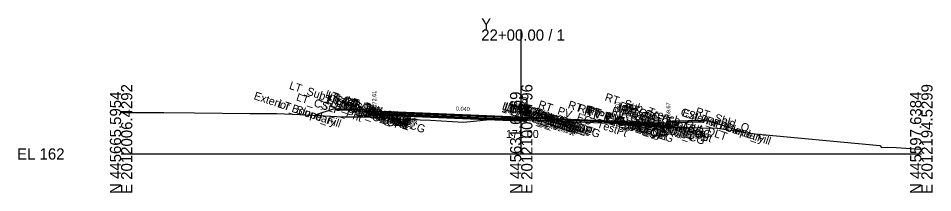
# Model space of a CAD drawing. Extents: x -26 to 3203, y -10 to 9532.
# Drawn here: x 974.3 to 1202.8, y 5990.3 to 6034 of the extents above; entities that cross this region are included whole.
import ezdxf

# ---------------------------------------------------------------- set-up
doc = ezdxf.new("R2010")
doc.units = 0
for name, color, linetype in [('Default', 7, 'Continuous'), ('Exist Cross Section Cell', 7, 'Continuous'), ('Exist XS Center Line Elevation Label', 7, 'Continuous'), ('Exist XS Ground Line', 7, 'Continuous'), ('Prop CMT Conc Surface', 7, 'Continuous'), ('Prop CMT Concrete Structures', 7, 'Continuous'), ('Prop CMT Pvmt Course 1', 7, 'Continuous'), ('Prop CMT Pvmt Course 1 CG', 7, 'Continuous'), ('Prop CMT Pvmt Course 1 Wedge', 7, 'Continuous'), ('Prop CMT Pvmt Course 2', 7, 'Continuous'), ('Prop CMT Pvmt Course 2 Wedge', 7, 'Continuous'), ('Prop CMT Pvmt Course 3', 7, 'Continuous'), ('Prop CMT Pvmt Surface', 7, 'Continuous'), ('Prop CMT Pvmt Wedge Surface 1', 7, 'Continuous'), ('Prop CMT Pvmt Wedge Surface 2', 7, 'Continuous'), ('Prop CMT Pvmt Wedge Surface 3', 7, 'Continuous'), ('Prop CMT Slope Grass', 7, 'Continuous'), ('Prop CMT Subgrade Earthwork', 7, 'Continuous'), ('Prop XS Hydro Elevations', 7, 'Continuous'), ('Prop XS Label Text', 7, 'Continuous'), ('Prop XS SE Text', 7, 'Continuous'), ('Prop XS Side Slope Text', 7, 'Continuous'), ('Scratch_Level_0', 7, 'Continuous')]:
    doc.layers.add(name, color=color, linetype=linetype)

msp = doc.modelspace()

# ---------------------------------------------------------------- linework, layer by layer
at = {"layer": 'Exist Cross Section Cell'}
for p, q in [((1100, 6000), (1100, 6031.15)), ((1000, 6000), (1100, 6000)), ((1100, 6000), (1200, 6000))]:
    msp.add_line(p, q, dxfattribs=at)
at = {"layer": 'Exist XS Ground Line'}
msp.add_lwpolyline([(1000, 6010.38), (1010.72, 6010.38), (1018.37, 6010.32), (1032.17, 6010.12), (1038.88, 6010.12), (1044.75, 6009.88), (1049.34, 6009.63), (1055.38, 6009.33), (1061.59, 6009.27), (1072.18, 6008.65), (1077.29, 6008.45), (1085.58, 6007.93), (1095.45, 6008.97), (1100.29, 6009), (1101.4, 6008.98), (1101.78, 6008.96), (1102.43, 6008.93), (1104.59, 6008.84), (1106.97, 6008.73), (1108.29, 6008.66), (1109.63, 6008.6), (1111.93, 6008.49), (1112.31, 6008.47), (1112.93, 6008.45), (1113.74, 6008.41), (1114.92, 6008.36), (1116.07, 6008.3), (1117.57, 6008.22), (1119.29, 6008.14), (1120.22, 6008.09), (1121.93, 6007.98), (1122.88, 6007.92), (1123.97, 6007.86), (1124.64, 6007.82), (1125.51, 6007.76), (1126.18, 6007.7), (1135.4, 6006.66), (1140.61, 6006.61), (1149.03, 6006.45), (1157.58, 6005.16), (1189.62, 6002.12), (1190.04, 6001.62), (1191.62, 6001.72), (1193.67, 6001.6), (1194.99, 6001.52), (1198.34, 6001.3), (1200, 6001.22)], dxfattribs=at)
at = {"layer": 'Prop CMT Conc Surface'}
for points in [[(1058.75, 6011.2), (1053.75, 6011.3)], [(1063.25, 6010.61), (1063.25, 6011.11), (1062.75, 6011.11)], [(1065.25, 6010.61), (1063.25, 6010.61)], [(1136.75, 6007.67), (1136.75, 6008.17), (1137.25, 6008.17)], [(1134.75, 6007.83), (1136.75, 6007.67)]]:
    msp.add_lwpolyline(points, dxfattribs=at)
at = {"layer": 'Prop CMT Concrete Structures'}
for points in [[(1053.75, 6010.97), (1053.75, 6011.3)], [(1053.75, 6011.3), (1058.75, 6011.2)], [(1058.75, 6010.87), (1053.75, 6010.97)], [(1058.75, 6011.2), (1058.75, 6010.87)], [(1065.25, 6010.61), (1063.25, 6010.61), (1063.25, 6011.11), (1062.75, 6011.11)], [(1062.75, 6011.11), (1062.75, 6010.13), (1065.25, 6010.03)], [(1065.25, 6010.03), (1065.25, 6010.61)], [(1108.5, 6008.88), (1108.49, 6009.05), (1107.74, 6009.3), (1107, 6009.43), (1106.26, 6009.42), (1105.51, 6009.17), (1105.5, 6009)], [(1105.5, 6009), (1108.5, 6008.88)], [(1134.75, 6007.83), (1136.75, 6007.67), (1136.75, 6008.17), (1137.25, 6008.17)], [(1137.25, 6008.17), (1137.25, 6007.15), (1134.75, 6007.25)], [(1145.75, 6008.35), (1137.75, 6008.19)], [(1137.75, 6008.19), (1137.75, 6007.86)], [(1145.75, 6008.02), (1145.75, 6008.35)], [(1134.75, 6007.25), (1134.75, 6007.83)], [(1137.75, 6007.86), (1145.75, 6008.02)]]:
    msp.add_lwpolyline(points, dxfattribs=at)
at = {"layer": 'Prop CMT Pvmt Course 1'}
for points in [[(1105.5, 6009), (1065.25, 6010.61)], [(1065.25, 6010.61), (1065.25, 6010.36)], [(1065.25, 6010.36), (1101.4, 6008.92)], [(1101.4, 6008.92), (1101.4, 6009.17)], [(1101.4, 6008.92), (1101.4, 6009.17)], [(1105.5, 6009), (1108.5, 6008.88)], [(1105.5, 6008.75), (1105.5, 6009)], [(1105.5, 6008.75), (1105.5, 6009)], [(1108.5, 6008.88), (1134.75, 6007.83)], [(1124.64, 6008.11), (1108.5, 6008.76)], [(1124.64, 6007.99), (1124.64, 6008.11)], [(1134.75, 6007.58), (1124.64, 6007.99)], [(1134.75, 6007.83), (1134.75, 6007.58)]]:
    msp.add_lwpolyline(points, dxfattribs=at)
for points in [[(1101.4, 6008.92), (1101.4, 6009.04), (1101.4, 6009.04), (1101.4, 6008.92)], [(1105.5, 6008.75), (1105.5, 6008.88), (1105.5, 6008.88), (1105.5, 6008.75)]]:
    msp.add_lwpolyline(points, close=True, dxfattribs=at)
at = {"layer": 'Prop CMT Pvmt Course 1 CG'}
for points in [[(1065.25, 6010.03), (1062.25, 6010.15), (1061.93, 6009.83)], [(1061.93, 6009.83), (1065.25, 6009.69)], [(1065.25, 6009.69), (1065.25, 6010.03)], [(1134.75, 6007.25), (1137.75, 6007.13), (1138.1, 6006.78)], [(1134.75, 6006.91), (1134.75, 6007.25)], [(1138.1, 6006.78), (1134.75, 6006.91)]]:
    msp.add_lwpolyline(points, dxfattribs=at)
at = {"layer": 'Prop CMT Pvmt Course 1 Wedge'}
for points in [[(1101.4, 6009.04), (1109.63, 6008.71), (1111.93, 6008.62), (1112.31, 6008.6), (1112.93, 6008.58), (1113.74, 6008.55), (1114.92, 6008.5), (1116.07, 6008.45), (1117.57, 6008.39), (1119.29, 6008.32), (1119.97, 6008.3), (1120.22, 6008.29), (1121.93, 6008.22), (1122.88, 6008.18), (1123.97, 6008.14), (1124.64, 6008.11)], [(1124.64, 6007.99), (1123.97, 6008.01), (1122.88, 6008.06), (1121.93, 6008.09), (1120.22, 6008.16), (1119.97, 6008.17), (1119.29, 6008.2), (1117.57, 6008.27), (1116.07, 6008.33), (1114.92, 6008.37), (1113.74, 6008.42), (1112.93, 6008.45), (1112.31, 6008.48), (1111.93, 6008.49), (1111.03, 6008.53), (1109.63, 6008.6), (1108.5, 6008.65)], [(1124.64, 6008.11), (1124.64, 6007.99), (1124.64, 6007.99)]]:
    msp.add_lwpolyline(points, dxfattribs=at)
at = {"layer": 'Prop CMT Pvmt Course 2'}
for points in [[(1101.4, 6008.92), (1065.25, 6010.36)], [(1065.25, 6010.36), (1065.25, 6010.03)], [(1065.25, 6010.03), (1101.4, 6008.58)], [(1101.4, 6008.58), (1101.4, 6008.92)], [(1101.4, 6008.58), (1101.4, 6008.92)], [(1124.64, 6007.65), (1124.64, 6007.99)], [(1124.64, 6007.99), (1134.75, 6007.58)], [(1134.75, 6007.25), (1124.64, 6007.65)], [(1134.75, 6007.58), (1134.75, 6007.25)]]:
    msp.add_lwpolyline(points, dxfattribs=at)
at = {"layer": 'Prop CMT Pvmt Course 2 Wedge'}
for points in [[(1126.18, 6007.7), (1126.09, 6007.71), (1125.51, 6007.76), (1125.39, 6007.77), (1125.29, 6007.78), (1124.64, 6007.82), (1123.97, 6007.86), (1122.88, 6007.92), (1121.93, 6007.98), (1120.22, 6008.09), (1119.97, 6008.1), (1119.29, 6008.14), (1117.57, 6008.22), (1116.07, 6008.3), (1114.92, 6008.36), (1113.74, 6008.41), (1112.93, 6008.45), (1112.31, 6008.47), (1111.93, 6008.49), (1111.03, 6008.53)], [(1111.03, 6008.53), (1111.93, 6008.49)], [(1111.93, 6008.49), (1112.31, 6008.48), (1112.93, 6008.45), (1113.74, 6008.42), (1114.92, 6008.37), (1116.07, 6008.33), (1117.57, 6008.27), (1119.29, 6008.2), (1119.97, 6008.17), (1120.22, 6008.16), (1121.93, 6008.09), (1122.88, 6008.06), (1123.97, 6008.01), (1124.64, 6007.99)], [(1124.64, 6007.99), (1124.64, 6007.77), (1124.64, 6007.77)]]:
    msp.add_lwpolyline(points, dxfattribs=at)
at = {"layer": 'Prop CMT Pvmt Course 3'}
for points in [[(1101.4, 6008.58), (1065.25, 6010.03)], [(1065.25, 6010.03), (1065.25, 6009.69)], [(1065.25, 6009.69), (1101.4, 6008.25)], [(1101.4, 6008.25), (1101.4, 6008.58)], [(1101.4, 6008.25), (1101.4, 6008.58)], [(1124.64, 6007.65), (1134.75, 6007.25)], [(1124.64, 6007.32), (1124.64, 6007.65)], [(1134.75, 6006.91), (1124.64, 6007.32)], [(1134.75, 6007.25), (1134.75, 6006.91)]]:
    msp.add_lwpolyline(points, dxfattribs=at)
at = {"layer": 'Prop CMT Pvmt Surface'}
for points in [[(1105.5, 6009), (1065.25, 6010.61)], [(1105.5, 6009), (1108.5, 6008.88)], [(1108.5, 6008.88), (1134.75, 6007.83)]]:
    msp.add_lwpolyline(points, dxfattribs=at)
at = {"layer": 'Prop CMT Pvmt Wedge Surface 1'}
for points in [[(1108.5, 6008.76), (1124.64, 6008.11)], [(1124.64, 6008.11), (1124.64, 6007.99)], [(1124.64, 6007.99), (1134.75, 6007.58)], [(1134.75, 6007.58), (1134.75, 6007.83)]]:
    msp.add_lwpolyline(points, dxfattribs=at)
at = {"layer": 'Prop CMT Pvmt Wedge Surface 2'}
for points in [[(1101.4, 6008.92), (1134.75, 6007.58)], [(1134.75, 6007.58), (1134.75, 6007.83)]]:
    msp.add_lwpolyline(points, dxfattribs=at)
at = {"layer": 'Prop CMT Pvmt Wedge Surface 3'}
for points in [[(1101.4, 6008.98), (1101.4, 6008.4)], [(1101.4, 6008.58), (1134.75, 6007.25)], [(1134.75, 6007.25), (1134.75, 6007.83)]]:
    msp.add_lwpolyline(points, dxfattribs=at)
at = {"layer": 'Prop CMT Slope Grass'}
for points in [[(1062.75, 6011.11), (1053.25, 6011.3), (1048.38, 6009.68)], [(1137.25, 6008.17), (1146.75, 6008.36)], [(1146.75, 6008.36), (1155.33, 6005.5)]]:
    msp.add_lwpolyline(points, dxfattribs=at)
at = {"layer": 'Prop CMT Subgrade Earthwork'}
for points in [[(1065.25, 6009.69), (1061.93, 6009.83), (1060.6, 6011.15)], [(1101.4, 6008.25), (1065.25, 6009.69)], [(1101.4, 6008.25), (1101.4, 6008.98)], [(1134.75, 6006.91), (1138.1, 6006.78), (1139.53, 6008.22)], [(1124.64, 6007.32), (1124.62, 6007.82)], [(1124.64, 6007.32), (1134.75, 6006.91)]]:
    msp.add_lwpolyline(points, dxfattribs=at)
at = {"layer": 'Prop XS Label Text'}
for p, q in [((1101.4, 6013.98), (1101.4, 6008.98)), ((1124.64, 6012.82), (1124.64, 6007.82))]:
    msp.add_line(p, q, dxfattribs=at)

# ---------------------------------------------------------------- texts
at = {"layer": 'Default'}
msp.add_text('-', height=0.0001, dxfattribs=at).set_placement((1000, 6000))
at = {"layer": 'Exist Cross Section Cell'}
for s, p in [('Y', (1090, 6031.15)), ('22+00.00 / 1', (1090, 6028.35)), ('EL 162', (974, 5998.6))]:
    msp.add_text(s, height=2.8, dxfattribs=at).set_placement(p)
for s, p in [('E 2012006.4292', (1002.8, 5990)), ('E 2012100.4796', (1102.8, 5990)), ('E 2012194.5299', (1202.8, 5990)), ('N 445665.5954', (1000, 5990)), ('N 445631.6169', (1100, 5990)), ('N 445597.6384', (1200, 5990))]:
    msp.add_text(s, height=2.8, rotation=90, dxfattribs=at).set_placement(p)
at = {"layer": 'Exist XS Center Line Elevation Label'}
msp.add_text('171.00', height=2, dxfattribs=at).set_placement((1096.19, 6004))
at = {"layer": 'Prop XS Hydro Elevations'}
for s, p in [('172.61', (1063.75, 6011.61)), ('169.67', (1137.25, 6008.67))]:
    msp.add_text(s, height=1, rotation=90, dxfattribs=at).set_placement(p)
at = {"layer": 'Prop XS Label Text'}
for p in [(1101.3, 6010), (1124.54, 6008.84)]:
    msp.add_text('E. EOT', height=1, rotation=90, dxfattribs=at).set_placement(p)
at = {"layer": 'Prop XS SE Text'}
for p in [(1083.67, 6010.88), (1119.92, 6009.43)]:
    msp.add_text('0.040', height=1, rotation=357.7094, dxfattribs=at).set_placement(p)
at = {"layer": 'Prop XS Side Slope Text'}
for rotation, p in [(18.4349, (1049.83, 6010.95)), (341.5651, (1150.44, 6007.92))]:
    msp.add_text('3:1', height=1, rotation=rotation, dxfattribs=at).set_placement(p)
at = {"layer": 'Scratch_Level_0'}
for s, p in [('LT_Sub_Trench_Out_DLT', (1041.85, 6016.35)), ('Exterior Boundary', (1033.02, 6013.75)), ('LT_CSLP_Pnt', (1043.61, 6013.46)), ('LT_CG1_Shelf_Out', (1049.18, 6013.45)), ('LT_CG_Top_Face', (1050.85, 6014.19)), ('LT_CG_Top_BOC', (1051.32, 6013.87)), ('LT_CG_Top_Gut', (1051.77, 6013.38)), ('RT_Sub_Trench_Out_DLT', (1120.74, 6013.43)), ('LT_Slope_Fill', (1039.07, 6011.73)), ('LT_CG_Bot_BOC', (1051.35, 6012.87)), ('LT_Sub_OEOP', (1052.23, 6012.01)), ('LT_Sub_OEOT_CG', (1052.95, 6012.74)), ('LT_CG_Bot_IE', (1055.36, 6012.27)), ('LT_Sub_OEOT', (1055.52, 6011.88)), ('LT_PV2_OEOT', (1055.61, 6012.52)), ('LT_PV3_OEOT', (1055.61, 6012.19)), ('LT_PV1_OEOT', (1056.15, 6012.59)), ('LT_PV2_OEEOP', (1095.04, 6011.18)), ('LT_PV1_OEEOP', (1095.58, 6011.13)), ('LT_PV2_IEEOP', (1095.65, 6010.98)), ('LT_PV1_IEEOP', (1096.19, 6010.93)), ('RT_PV_IEEOP_EG', (1096.93, 6011.45)), ('RT_PV2_IEEOP', (1098.61, 6010.87)), ('MI_Face Out', (1098.94, 6011.18)), ('MI_Top Out', (1099.1, 6011.12)), ('RT_PV_EG_TestPt', (1104.09, 6011.6)), ('RT_PV_Sub_Tie_Out', (1111.52, 6011.53)), ('RT_CG_Top_Face', (1124.3, 6011.27)), ('RT_CG_Top_BOC', (1125.77, 6010.94)), ('LT_Sub_OEEOP', (1094.95, 6010.55)), ('LT_PV3_OEEOP', (1095.04, 6010.85)), ('LT_PV2_PGL1', (1096.53, 6010.69)), ('LT_PV3_PGL1', (1096.53, 6010.35)), ('LT_PV2_PGL', (1096.85, 6010.58)), ('LT_PV4_PGL', (1096.85, 6009.91)), ('LT_PV1_PGL', (1097.39, 6010.65)), ('MI_Face In', (1097.5, 6010.78)), ('RT_PV3_IEEOP', (1098.61, 6010.54)), ('RT_PV1_IEEOP', (1099.15, 6010.82)), ('MI_Top In', (1099.16, 6010.73)), ('RT_PV2_PGL1', (1099.49, 6010.58)), ('RT_PV3_PGL1', (1099.49, 6010.25)), ('RT_PV2_PGL', (1099.8, 6010.48)), ('RT_PV3_PGL', (1099.8, 6010.14)), ('RT_PV4_PGL', (1099.8, 6009.81)), ('MI_Bot Out', (1099.89, 6010.7)), ('MI_Crown', (1100.11, 6010.68)), ('RT_PV1_PGL', (1100.34, 6010.55)), ('RT_PV_OEEOP_EG', (1114, 6010.71)), ('RT_Sub_OEEOP', (1115.58, 6009.74)), ('RT_PV2_OEEOP', (1115.67, 6010.37)), ('RT_PV3_OEEOP', (1115.67, 6010.04)), ('RT_PV1_OEEOP', (1116.21, 6010.32)), ('RT_Sub_OEOT_CG', (1122.41, 6009.97)), ('RT_CG1_Shelf_Out', (1124.63, 6010.45)), ('RT_CG_Bot_IE', (1124.82, 6009.5)), ('RT_Sub_OEOT', (1124.98, 6009.12)), ('RT_PV2_OEOT', (1125.07, 6009.76)), ('RT_PV3_OEOT', (1125.07, 6009.42)), ('RT_CG_Top_Gut', (1125.23, 6010.46)), ('RT_PV1_OEOT', (1125.6, 6009.83)), ('RT_CG_Bot_BOC', (1125.8, 6009.91)), ('RT_Sub_OEOP', (1128.35, 6008.97)), ('CSLP_Pnt', (1139.67, 6009.67)), ('Exterior Boundary', (1140.07, 6009.53)), ('RT_Shld_O', (1143.35, 6009.85)), ('RT_Slope_Fill', (1146.08, 6007.53))]:
    msp.add_text(s, height=2, rotation=341.5651, dxfattribs=at).set_placement(p)

doc.saveas('drawing.dxf')
